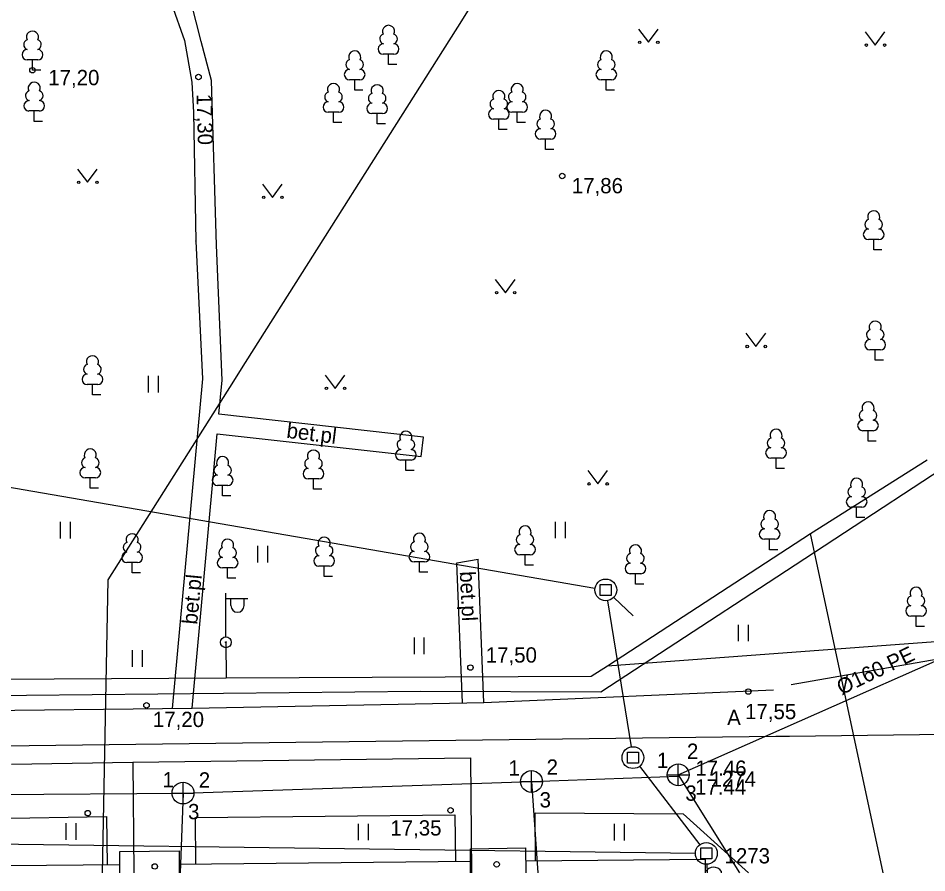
# Model space of a CAD drawing. Extents: x 713540 to 713867, y 6589774 to 6590061.
# Drawn here: x 713767.39 to 713808.98, y 6589774.07 to 6589813.21 of the extents above; entities that cross this region are included whole.
import ezdxf

# ---------------------------------------------------------------- set-up
doc = ezdxf.new("R2010")
doc.units = 0
for name, color, linetype in [('DKAEV', 7, 'Continuous'), ('HALJASTUS', 7, 'Continuous'), ('HOONE', 7, 'Continuous'), ('HOONEDET', 7, 'Continuous'), ('KKAEV', 7, 'Continuous'), ('KORGUS', 7, 'Continuous'), ('KTRASS', 7, 'Continuous'), ('MPKAABEL', 7, 'Continuous'), ('POST', 7, 'Continuous'), ('PUU', 7, 'Continuous'), ('SIKAEV', 7, 'Continuous'), ('SITRASS', 7, 'Continuous'), ('TEE', 7, 'Continuous'), ('TORU NR', 7, 'Continuous'), ('VEEKOGU', 7, 'Continuous'), ('VTRASS', 7, 'Continuous')]:
    doc.layers.add(name, color=color, linetype=linetype)

msp = doc.modelspace()

# ---------------------------------------------------------------- linework, layer by layer
at = {"layer": 'DKAEV'}
for p, q in [((713794.034, 6589786.773), (713794.034, 6589787.273)), ((713794.034, 6589787.273), (713794.534, 6589787.273)), ((713794.534, 6589787.273), (713794.534, 6589786.773)), ((713794.534, 6589786.773), (713794.034, 6589786.773)), ((713795.278, 6589779.094), (713795.278, 6589779.594)), ((713795.278, 6589779.594), (713795.778, 6589779.594)), ((713795.778, 6589779.594), (713795.778, 6589779.094)), ((713795.778, 6589779.094), (713795.278, 6589779.094)), ((713798.64, 6589774.708), (713798.64, 6589775.208)), ((713798.64, 6589775.208), (713799.14, 6589775.208)), ((713799.14, 6589775.208), (713799.14, 6589774.708)), ((713799.14, 6589774.708), (713798.64, 6589774.708))]:
    msp.add_line(p, q, dxfattribs=at)
for centre in [(713794.284, 6589787.023), (713795.528, 6589779.344), (713798.89, 6589774.958)]:
    msp.add_circle(centre, 0.5, dxfattribs=at)
at = {"layer": 'HALJASTUS'}
for p, q in [((713795.777, 6589812.707), (713796.24, 6589812.1)), ((713796.24, 6589812.1), (713796.686, 6589812.707)), ((713806.157, 6589812.577), (713806.62, 6589811.97)), ((713806.62, 6589811.97), (713807.066, 6589812.577)), ((713770.097, 6589806.297), (713770.56, 6589805.69)), ((713770.56, 6589805.69), (713771.006, 6589806.297)), ((713778.567, 6589805.607), (713779.03, 6589805)), ((713779.03, 6589805), (713779.476, 6589805.607)), ((713789.227, 6589801.237), (713789.69, 6589800.63)), ((713789.69, 6589800.63), (713790.136, 6589801.237)), ((713800.697, 6589798.777), (713801.16, 6589798.17)), ((713801.16, 6589798.17), (713801.606, 6589798.777)), ((713773.342, 6589796.823), (713773.342, 6589796.062)), ((713773.797, 6589796.823), (713773.797, 6589796.062)), ((713781.437, 6589796.857), (713781.9, 6589796.25)), ((713781.9, 6589796.25), (713782.346, 6589796.857)), ((713793.457, 6589792.487), (713793.92, 6589791.88)), ((713793.92, 6589791.88), (713794.366, 6589792.487)), ((713769.311, 6589790.145), (713769.311, 6589789.384)), ((713769.766, 6589790.145), (713769.766, 6589789.384)), ((713791.975, 6589790.148), (713791.975, 6589789.387)), ((713792.43, 6589790.148), (713792.43, 6589789.387)), ((713778.348, 6589789.036), (713778.348, 6589788.274)), ((713778.803, 6589789.036), (713778.803, 6589788.274)), ((713800.353, 6589785.432), (713800.353, 6589784.671)), ((713800.808, 6589785.432), (713800.808, 6589784.671)), ((713785.506, 6589784.849), (713785.506, 6589784.088)), ((713785.961, 6589784.849), (713785.961, 6589784.088)), ((713772.599, 6589784.263), (713772.599, 6589783.502)), ((713773.054, 6589784.263), (713773.054, 6589783.502)), ((713769.563, 6589776.344), (713769.563, 6589775.583)), ((713770.018, 6589776.344), (713770.018, 6589775.583)), ((713782.948, 6589776.318), (713782.948, 6589775.557)), ((713783.403, 6589776.318), (713783.403, 6589775.557)), ((713794.669, 6589776.314), (713794.669, 6589775.553)), ((713795.124, 6589776.314), (713795.124, 6589775.553))]:
    msp.add_line(p, q, dxfattribs=at)
for centre in [(713795.839, 6589812.1), (713796.668, 6589812.1), (713806.219, 6589811.97), (713807.048, 6589811.97), (713770.159, 6589805.69), (713770.988, 6589805.69), (713778.629, 6589805), (713779.458, 6589805), (713789.289, 6589800.63), (713790.118, 6589800.63), (713800.759, 6589798.17), (713801.588, 6589798.17), (713781.499, 6589796.25), (713782.328, 6589796.25), (713793.519, 6589791.88), (713794.348, 6589791.88)]:
    msp.add_circle(centre, 0.055, dxfattribs=at)
at = {"layer": 'HOONE'}
for points in [[(713704.798, 6589774.068), (713704.5, 6589777.88), (713726.25, 6589779.19), (713756.88, 6589779.76), (713802.063, 6589780.323), (713802.696, 6589780.331), (713812.22, 6589780.45), (713824.89, 6589807.23), (713827.83, 6589806.02)], [(713724.813, 6589799.015), (713793.791, 6589787.108)], [(713794.648, 6589786.681), (713795.546, 6589785.837)], [(713794.364, 6589786.53), (713795.448, 6589779.838)], [(713767.08, 6589779.045), (713772.63, 6589779.13), (713788.09, 6589779.34)], [(713772.63, 6589779.13), (713772.677, 6589774.068)], [(713788.09, 6589779.34), (713788.139, 6589774.068)], [(713795.832, 6589778.947), (713798.586, 6589775.355)], [(713766.244, 6589775.389), (713798.391, 6589774.964)], [(713772.046, 6589774.068), (713772.037, 6589775.043), (713774.75, 6589775.08), (713774.759, 6589774.068)], [(713788.095, 6589774.068), (713788.085, 6589775.169), (713790.615, 6589775.215), (713790.625, 6589774.068)], [(713798.909, 6589774.458), (713798.924, 6589774.068)]]:
    msp.add_lwpolyline(points, dxfattribs=at)
at = {"layer": 'KKAEV'}
for p, q in [((713790.882, 6589777.747), (713790.882, 6589778.747)), ((713797.603, 6589778.057), (713797.603, 6589779.057)), ((713797.103, 6589778.557), (713798.103, 6589778.557)), ((713774.932, 6589777.221), (713774.932, 6589778.221)), ((713790.382, 6589778.247), (713791.382, 6589778.247)), ((713774.432, 6589777.721), (713775.432, 6589777.721))]:
    msp.add_line(p, q, dxfattribs=at)
for centre in [(713790.882, 6589778.247), (713797.603, 6589778.557), (713774.932, 6589777.721)]:
    msp.add_circle(centre, 0.5, dxfattribs=at)
at = {"layer": 'KORGUS'}
for centre in [(713768.04, 6589810.82), (713775.64, 6589810.51), (713792.29, 6589805.98), (713788.09, 6589783.47), (713800.81, 6589782.37), (713773.26, 6589781.74), (713787.18, 6589776.93), (713770.57, 6589776.8), (713789.29, 6589774.46), (713773.64, 6589774.36)]:
    msp.add_circle(centre, 0.125, dxfattribs=at)
at = {"layer": 'KTRASS'}
for p, q in [((713790.882, 6589778.247), (713797.596, 6589778.501)), ((713774.932, 6589777.721), (713790.882, 6589778.247)), ((713790.882, 6589778.247), (713791.169, 6589774.068)), ((713758.53, 6589777.581), (713774.932, 6589777.721)), ((713774.932, 6589777.721), (713774.794, 6589774.068))]:
    msp.add_line(p, q, dxfattribs=at)
for points in [[(713797.603, 6589778.557), (713816.506, 6589786.914)], [(713797.603, 6589778.557), (713800.401, 6589774.068)]]:
    msp.add_lwpolyline(points, dxfattribs=at)
at = {"layer": 'MPKAABEL'}
for points in [[(713794.36, 6589783.55), (713811.85, 6589784.85), (713820.33, 6589802.68), (713827.71, 6589818.51), (713829.28, 6589821.92), (713828.25, 6589822.28), (713827.51, 6589821.7)], [(713733.277, 6589792.111), (713733.27, 6589793.4), (713736.06, 6589795.98), (713742.16, 6589795.93), (713742.89, 6589782.79), (713745.398, 6589782.812), (713776.9, 6589782.991), (713793.62, 6589783.07), (713794.36, 6589783.55), (713803.66, 6589789.6), (713809, 6589792.98)], [(713806.991, 6589774.068), (713803.66, 6589789.6)], [(713776.893, 6589784.627), (713776.9, 6589782.991)]]:
    msp.add_lwpolyline(points, dxfattribs=at)
at = {"layer": 'POST'}
for p, q in [((713776.893, 6589784.877), (713776.893, 6589786.877)), ((713776.893, 6589786.627), (713777.893, 6589786.627)), ((713777.119, 6589786.306), (713777.119, 6589786.627)), ((713777.732, 6589786.306), (713777.732, 6589786.627))]:
    msp.add_line(p, q, dxfattribs=at)
for radius in [0.25, 0.0234]:
    msp.add_circle((713776.893, 6589784.627), radius, dxfattribs=at)
msp.add_arc((713777.426, 6589786.306), 0.306, 180, 0, dxfattribs=at)
at = {"layer": 'PUU'}
for p, q in [((713784.58, 6589811.555), (713784.1, 6589811.555)), ((713784.34, 6589811.08), (713784.34, 6589811.555)), ((713768.28, 6589811.295), (713767.8, 6589811.295)), ((713768.04, 6589810.82), (713768.04, 6589811.295)), ((713768.42, 6589810.82), (713768.04, 6589810.82)), ((713784.72, 6589811.08), (713784.34, 6589811.08)), ((713783.03, 6589810.385), (713782.55, 6589810.385)), ((713782.79, 6589809.91), (713782.79, 6589810.385)), ((713794.55, 6589810.385), (713794.07, 6589810.385)), ((713794.31, 6589809.91), (713794.31, 6589810.385)), ((713783.17, 6589809.91), (713782.79, 6589809.91)), ((713794.69, 6589809.91), (713794.31, 6589809.91)), ((713768.36, 6589808.955), (713767.88, 6589808.955)), ((713768.12, 6589808.48), (713768.12, 6589808.955)), ((713782.06, 6589808.895), (713781.58, 6589808.895)), ((713781.82, 6589808.42), (713781.82, 6589808.895)), ((713784.06, 6589808.835), (713783.58, 6589808.835)), ((713783.82, 6589808.36), (713783.82, 6589808.835)), ((713790.47, 6589808.895), (713789.99, 6589808.895)), ((713790.23, 6589808.42), (713790.23, 6589808.895)), ((713768.5, 6589808.48), (713768.12, 6589808.48)), ((713782.2, 6589808.42), (713781.82, 6589808.42)), ((713784.2, 6589808.36), (713783.82, 6589808.36)), ((713789.63, 6589808.575), (713789.15, 6589808.575)), ((713789.39, 6589808.1), (713789.39, 6589808.575)), ((713790.61, 6589808.42), (713790.23, 6589808.42)), ((713789.77, 6589808.1), (713789.39, 6589808.1)), ((713791.77, 6589807.665), (713791.29, 6589807.665)), ((713791.53, 6589807.19), (713791.53, 6589807.665)), ((713791.91, 6589807.19), (713791.53, 6589807.19)), ((713806.79, 6589803.065), (713806.31, 6589803.065)), ((713806.55, 6589802.59), (713806.55, 6589803.065)), ((713806.93, 6589802.59), (713806.55, 6589802.59)), ((713806.86, 6589798.015), (713806.38, 6589798.015)), ((713806.62, 6589797.54), (713806.62, 6589798.015)), ((713807, 6589797.54), (713806.62, 6589797.54)), ((713771.025, 6589796.427), (713770.545, 6589796.427)), ((713770.785, 6589795.952), (713770.785, 6589796.427)), ((713771.165, 6589795.952), (713770.785, 6589795.952)), ((713806.53, 6589794.315), (713806.05, 6589794.315)), ((713806.29, 6589793.84), (713806.29, 6589794.315)), ((713806.67, 6589793.84), (713806.29, 6589793.84)), ((713785.373, 6589792.971), (713784.893, 6589792.971)), ((713785.133, 6589792.496), (713785.133, 6589792.971)), ((713802.32, 6589793.057), (713801.84, 6589793.057)), ((713802.08, 6589792.582), (713802.08, 6589793.057)), ((713785.513, 6589792.496), (713785.133, 6589792.496)), ((713802.46, 6589792.582), (713802.08, 6589792.582)), ((713770.926, 6589792.155), (713770.446, 6589792.155)), ((713770.686, 6589791.68), (713770.686, 6589792.155)), ((713781.145, 6589792.106), (713780.665, 6589792.106)), ((713780.905, 6589791.631), (713780.905, 6589792.106)), ((713771.066, 6589791.68), (713770.686, 6589791.68)), ((713776.985, 6589791.805), (713776.505, 6589791.805)), ((713776.745, 6589791.33), (713776.745, 6589791.805)), ((713781.285, 6589791.631), (713780.905, 6589791.631)), ((713777.125, 6589791.33), (713776.745, 6589791.33)), ((713806.01, 6589790.815), (713805.53, 6589790.815)), ((713805.77, 6589790.34), (713805.77, 6589790.815)), ((713806.15, 6589790.34), (713805.77, 6589790.34)), ((713802.027, 6589789.341), (713801.547, 6589789.341)), ((713801.787, 6589788.866), (713801.787, 6589789.341)), ((713802.167, 6589788.866), (713801.787, 6589788.866)), ((713772.842, 6589788.276), (713772.362, 6589788.276)), ((713772.602, 6589787.801), (713772.602, 6589788.276)), ((713785.992, 6589788.304), (713785.512, 6589788.304)), ((713785.752, 6589787.829), (713785.752, 6589788.304)), ((713790.83, 6589788.63), (713790.35, 6589788.63)), ((713790.59, 6589788.155), (713790.59, 6589788.63)), ((713777.215, 6589788.03), (713776.735, 6589788.03)), ((713776.975, 6589787.555), (713776.975, 6589788.03)), ((713781.634, 6589788.112), (713781.154, 6589788.112)), ((713781.394, 6589787.637), (713781.394, 6589788.112)), ((713790.97, 6589788.155), (713790.59, 6589788.155)), ((713772.982, 6589787.801), (713772.602, 6589787.801)), ((713777.355, 6589787.555), (713776.975, 6589787.555)), ((713781.774, 6589787.637), (713781.394, 6589787.637)), ((713786.132, 6589787.829), (713785.752, 6589787.829)), ((713795.883, 6589787.767), (713795.403, 6589787.767)), ((713795.643, 6589787.292), (713795.643, 6589787.767)), ((713796.023, 6589787.292), (713795.643, 6589787.292)), ((713808.73, 6589785.825), (713808.25, 6589785.825)), ((713808.49, 6589785.35), (713808.49, 6589785.825)), ((713808.87, 6589785.35), (713808.49, 6589785.35))]:
    msp.add_line(p, q, dxfattribs=at)
for centre, radius, start, end in [((713784.34, 6589812.6), 0.277, 332.5799, 207.4201), ((713768.04, 6589812.34), 0.277, 332.5799, 207.4201), ((713784.17, 6589812.253), 0.233, 109.0217, 253.1415), ((713784.51, 6589812.253), 0.233, 286.8508, 70.9859), ((713767.87, 6589811.993), 0.233, 109.0217, 253.1415), ((713768.21, 6589811.993), 0.233, 286.8508, 70.9859), ((713784.103, 6589811.792), 0.238, 90.0016, 269.3953), ((713784.577, 6589811.792), 0.238, 270.6047, 89.9984), ((713767.803, 6589811.532), 0.238, 90.0016, 269.3953), ((713768.277, 6589811.532), 0.238, 270.6047, 89.9984), ((713782.79, 6589811.43), 0.277, 332.5799, 207.4201), ((713794.31, 6589811.43), 0.277, 332.5799, 207.4201), ((713782.62, 6589811.083), 0.233, 109.0217, 253.1415), ((713782.96, 6589811.083), 0.233, 286.8508, 70.9859), ((713794.14, 6589811.083), 0.233, 109.0217, 253.1415), ((713794.48, 6589811.083), 0.233, 286.8508, 70.9859), ((713782.553, 6589810.622), 0.238, 90.0016, 269.3953), ((713783.027, 6589810.622), 0.238, 270.6047, 89.9984), ((713794.073, 6589810.622), 0.238, 90.0016, 269.3953), ((713794.547, 6589810.622), 0.238, 270.6047, 89.9984), ((713768.12, 6589810), 0.277, 332.5799, 207.4201), ((713781.82, 6589809.94), 0.277, 332.5799, 207.4201), ((713783.82, 6589809.88), 0.277, 332.5799, 207.4201), ((713789.39, 6589809.62), 0.277, 332.5799, 207.4201), ((713790.23, 6589809.94), 0.277, 332.5799, 207.4201), ((713767.95, 6589809.653), 0.233, 109.0217, 253.1415), ((713768.29, 6589809.653), 0.233, 286.8508, 70.9859), ((713781.65, 6589809.593), 0.233, 109.0217, 253.1415), ((713781.99, 6589809.593), 0.233, 286.8508, 70.9859), ((713783.65, 6589809.533), 0.233, 109.0217, 253.1415), ((713783.99, 6589809.533), 0.233, 286.8508, 70.9859), ((713789.22, 6589809.273), 0.233, 109.0217, 253.1415), ((713789.56, 6589809.273), 0.233, 286.8508, 70.9859), ((713790.06, 6589809.593), 0.233, 109.0217, 253.1415), ((713790.4, 6589809.593), 0.233, 286.8508, 70.9859), ((713767.883, 6589809.192), 0.238, 90.0016, 269.3953), ((713768.357, 6589809.192), 0.238, 270.6047, 89.9984), ((713781.583, 6589809.132), 0.238, 90.0016, 269.3953), ((713782.057, 6589809.132), 0.238, 270.6047, 89.9984), ((713783.583, 6589809.072), 0.238, 90.0016, 269.3953), ((713784.057, 6589809.072), 0.238, 270.6047, 89.9984), ((713789.993, 6589809.132), 0.238, 90.0016, 269.3953), ((713790.467, 6589809.132), 0.238, 270.6047, 89.9984), ((713789.153, 6589808.812), 0.238, 90.0016, 269.3953), ((713789.627, 6589808.812), 0.238, 270.6047, 89.9984), ((713791.53, 6589808.71), 0.277, 332.5799, 207.4201), ((713791.36, 6589808.363), 0.233, 109.0217, 253.1415), ((713791.7, 6589808.363), 0.233, 286.8508, 70.9859), ((713791.293, 6589807.902), 0.238, 90.0016, 269.3953), ((713791.767, 6589807.902), 0.238, 270.6047, 89.9984), ((713806.55, 6589804.11), 0.277, 332.5799, 207.4201), ((713806.38, 6589803.763), 0.233, 109.0217, 253.1415), ((713806.72, 6589803.763), 0.233, 286.8508, 70.9859), ((713806.313, 6589803.302), 0.238, 90.0016, 269.3953), ((713806.787, 6589803.302), 0.238, 270.6047, 89.9984), ((713806.62, 6589799.06), 0.277, 332.5799, 207.4201), ((713806.45, 6589798.713), 0.233, 109.0217, 253.1415), ((713806.79, 6589798.713), 0.233, 286.8508, 70.9859), ((713806.383, 6589798.252), 0.238, 90.0016, 269.3953), ((713806.857, 6589798.252), 0.238, 270.6047, 89.9984), ((713770.785, 6589797.472), 0.277, 332.5799, 207.4201), ((713770.615, 6589797.125), 0.233, 109.0217, 253.1415), ((713770.955, 6589797.125), 0.233, 286.8508, 70.9859), ((713770.547, 6589796.665), 0.238, 90.0016, 269.3953), ((713771.022, 6589796.665), 0.238, 270.6047, 89.9984), ((713806.29, 6589795.36), 0.277, 332.5799, 207.4201), ((713806.12, 6589795.013), 0.233, 109.0217, 253.1415), ((713806.46, 6589795.013), 0.233, 286.8508, 70.9859), ((713806.053, 6589794.552), 0.238, 90.0016, 269.3953), ((713806.527, 6589794.552), 0.238, 270.6047, 89.9984), ((713785.133, 6589794.016), 0.277, 332.5799, 207.4201), ((713802.08, 6589794.102), 0.277, 332.5799, 207.4201), ((713784.963, 6589793.669), 0.233, 109.0217, 253.1415), ((713785.304, 6589793.669), 0.233, 286.8508, 70.9859), ((713801.91, 6589793.754), 0.233, 109.0217, 253.1415), ((713802.25, 6589793.754), 0.233, 286.8508, 70.9859), ((713770.686, 6589793.2), 0.277, 332.5799, 207.4201), ((713780.905, 6589793.151), 0.277, 332.5799, 207.4201), ((713784.896, 6589793.209), 0.238, 90.0016, 269.3953), ((713785.371, 6589793.209), 0.238, 270.6047, 89.9984), ((713801.842, 6589793.294), 0.238, 90.0016, 269.3953), ((713802.317, 6589793.294), 0.238, 270.6047, 89.9984), ((713770.516, 6589792.853), 0.233, 109.0217, 253.1415), ((713770.856, 6589792.853), 0.233, 286.8508, 70.9859), ((713776.745, 6589792.85), 0.277, 332.5799, 207.4201), ((713780.735, 6589792.803), 0.233, 109.0217, 253.1415), ((713781.075, 6589792.803), 0.233, 286.8508, 70.9859), ((713770.449, 6589792.392), 0.238, 90.0016, 269.3953), ((713770.924, 6589792.392), 0.238, 270.6047, 89.9984), ((713776.575, 6589792.503), 0.233, 109.0217, 253.1415), ((713776.915, 6589792.503), 0.233, 286.8508, 70.9859), ((713780.668, 6589792.343), 0.238, 90.0016, 269.3953), ((713781.143, 6589792.343), 0.238, 270.6047, 89.9984), ((713776.507, 6589792.043), 0.238, 90.0016, 269.3953), ((713776.982, 6589792.043), 0.238, 270.6047, 89.9984), ((713805.77, 6589791.86), 0.277, 332.5799, 207.4201), ((713805.6, 6589791.513), 0.233, 109.0217, 253.1415), ((713805.94, 6589791.513), 0.233, 286.8508, 70.9859), ((713805.533, 6589791.052), 0.238, 90.0016, 269.3953), ((713806.007, 6589791.052), 0.238, 270.6047, 89.9984), ((713801.787, 6589790.386), 0.277, 332.5799, 207.4201), ((713790.59, 6589789.675), 0.277, 332.5799, 207.4201), ((713801.617, 6589790.038), 0.233, 109.0217, 253.1415), ((713801.957, 6589790.038), 0.233, 286.8508, 70.9859), ((713772.602, 6589789.321), 0.277, 332.5799, 207.4201), ((713785.752, 6589789.349), 0.277, 332.5799, 207.4201), ((713790.42, 6589789.328), 0.233, 109.0217, 253.1415), ((713790.76, 6589789.328), 0.233, 286.8508, 70.9859), ((713801.549, 6589789.578), 0.238, 90.0016, 269.3953), ((713802.024, 6589789.578), 0.238, 270.6047, 89.9984), ((713772.432, 6589788.973), 0.233, 109.0217, 253.1415), ((713772.772, 6589788.973), 0.233, 286.8508, 70.9859), ((713776.975, 6589789.075), 0.277, 332.5799, 207.4201), ((713781.394, 6589789.157), 0.277, 332.5799, 207.4201), ((713785.582, 6589789.001), 0.233, 109.0217, 253.1415), ((713785.922, 6589789.001), 0.233, 286.8508, 70.9859), ((713790.352, 6589788.868), 0.238, 90.0016, 269.3953), ((713790.827, 6589788.868), 0.238, 270.6047, 89.9984), ((713795.643, 6589788.812), 0.277, 332.5799, 207.4201), ((713772.365, 6589788.513), 0.238, 90.0016, 269.3953), ((713772.84, 6589788.513), 0.238, 270.6047, 89.9984), ((713776.805, 6589788.728), 0.233, 109.0217, 253.1415), ((713777.145, 6589788.728), 0.233, 286.8508, 70.9859), ((713781.224, 6589788.81), 0.233, 109.0217, 253.1415), ((713781.564, 6589788.81), 0.233, 286.8508, 70.9859), ((713785.514, 6589788.541), 0.238, 90.0016, 269.3953), ((713785.989, 6589788.541), 0.238, 270.6047, 89.9984), ((713795.473, 6589788.465), 0.233, 109.0217, 253.1415), ((713795.813, 6589788.465), 0.233, 286.8508, 70.9859), ((713776.737, 6589788.268), 0.238, 90.0016, 269.3953), ((713777.212, 6589788.268), 0.238, 270.6047, 89.9984), ((713781.157, 6589788.349), 0.238, 90.0016, 269.3953), ((713781.632, 6589788.349), 0.238, 270.6047, 89.9984), ((713795.406, 6589788.005), 0.238, 90.0016, 269.3953), ((713795.881, 6589788.005), 0.238, 270.6047, 89.9984), ((713808.49, 6589786.87), 0.277, 332.5799, 207.4201), ((713808.32, 6589786.523), 0.233, 109.0217, 253.1415), ((713808.66, 6589786.523), 0.233, 286.8508, 70.9859), ((713808.253, 6589786.062), 0.238, 90.0016, 269.3953), ((713808.727, 6589786.062), 0.238, 270.6047, 89.9984)]:
    msp.add_arc(centre, radius, start, end, dxfattribs=at)
at = {"layer": 'SITRASS'}
msp.add_lwpolyline([(713726.305, 6589783.201), (713726.59, 6589783.58), (713728.41, 6589783.99), (713737.91, 6589784.56), (713742.79, 6589781.97), (713755.73, 6589782.08), (713785.81, 6589782.39), (713794.06, 6589782.35), (713801.725, 6589787.367), (713802.954, 6589788.171), (713811.95, 6589794.06), (713820.13, 6589802.81), (713825.16, 6589813.2), (713832.56, 6589810.04)], dxfattribs=at)
at = {"layer": 'TEE'}
for points in [[(713771.12, 6589822.71), (713773.03, 6589817.14), (713774.41, 6589813.86), (713775, 6589812.19), (713775.33, 6589810.27), (713775.41, 6589808.89), (713775.523, 6589802.99), (713775.52, 6589803.002), (713775.523, 6589802.99), (713775.82, 6589796.687), (713774.442, 6589781.6)], [(713775.346, 6589781.61), (713776.493, 6589794.168), (713785.839, 6589793.127), (713785.938, 6589794.022), (713776.575, 6589795.065), (713776.717, 6589796.622), (713776.469, 6589802.811), (713776.23, 6589810.35), (713775.76, 6589812.13), (713775.31, 6589813.94), (713773.93, 6589817.22), (713771.94, 6589822.75)], [(713787.474, 6589788.262), (713788.444, 6589788.436)], [(713787.722, 6589781.849), (713787.474, 6589788.262)], [(713788.698, 6589781.868), (713788.444, 6589788.436)], [(713813.12, 6589786.46), (713812.47, 6589785.05), (713812.03, 6589784.3), (713802.773, 6589782.673)], [(713737.195, 6589781.213), (713753.691, 6589781.368), (713775.346, 6589781.61), (713788.698, 6589781.868), (713801.96, 6589782.454)], [(713759.151, 6589774.31), (713759.132, 6589776.432), (713771.432, 6589776.643), (713771.453, 6589774.425)], [(713775.518, 6589774.463), (713775.498, 6589776.608), (713787.382, 6589776.717), (713787.402, 6589774.574)], [(713791.074, 6589774.609), (713791.053, 6589776.822), (713797.824, 6589776.768)], [(713800.814, 6589774.068), (713797.824, 6589776.768)], [(713788.091, 6589774.581), (713774.755, 6589774.456)], [(713798.854, 6589774.068), (713798.849, 6589774.681), (713790.62, 6589774.604)], [(713772.043, 6589774.431), (713758.618, 6589774.305)]]:
    msp.add_lwpolyline(points, dxfattribs=at)
at = {"layer": 'VEEKOGU'}
for points in [[(713798.853, 6589774.068), (713798.853, 6589774.132)], [(713799.569, 6589774.138), (713799.569, 6589774.068)]]:
    msp.add_lwpolyline(points, dxfattribs=at)
msp.add_arc((713799.213, 6589773.893), 0.432, 34.4244, 146.4047, dxfattribs=at)
at = {"layer": 'VTRASS'}
msp.add_lwpolyline([(713771.246, 6589774.068), (713771.5, 6589787.48), (713777.257, 6589796.582), (713777.609, 6589797.14), (713787.69, 6589813.08), (713794.35, 6589823.75)], dxfattribs=at)

# ---------------------------------------------------------------- texts
at = {"layer": 'HOONEDET'}
for rotation, p in [(352.8785, (713779.643, 6589793.992)), (84.5936, (713775.577, 6589785.42)), (272.8077, (713787.599, 6589787.863))]:
    msp.add_text('bet.pl', height=0.7, rotation=rotation, dxfattribs=at).set_placement(p)
at = {"layer": 'KORGUS'}
for s, p in [('17,20', (713768.761, 6589810.135)), ('17,86', (713792.73, 6589805.185)), ('17,50', (713788.791, 6589783.695)), ('17,55', (713800.663, 6589781.105)), ('17,20', (713773.551, 6589780.745)), ('17.46', (713798.387, 6589778.511)), ('17.44', (713798.374, 6589777.647)), ('17,35', (713784.423, 6589775.775))]:
    msp.add_text(s, height=0.7, dxfattribs=at).set_placement(p)
msp.add_text('17,30', height=0.7, rotation=271.5014, dxfattribs=at).set_placement((713775.552, 6589809.731))
at = {"layer": 'KTRASS'}
msp.add_text('%%c160 PE', height=0.7, rotation=25.6958, dxfattribs=at).set_placement((713805.071, 6589782.199))
at = {"layer": 'SIKAEV'}
for s, p in [('1274', (713799.08, 6589778.02)), ('1273', (713799.72, 6589774.5))]:
    msp.add_text(s, height=0.7, dxfattribs=at).set_placement(p)
at = {"layer": 'TEE'}
msp.add_text('A', height=0.7, dxfattribs=at).set_placement((713799.843, 6589780.834))
at = {"layer": 'TORU NR'}
for s, p in [('2', (713798.001, 6589779.286)), ('1', (713796.625, 6589778.868)), ('1', (713789.831, 6589778.524)), ('2', (713791.576, 6589778.561)), ('1', (713773.994, 6589777.983)), ('2', (713775.653, 6589777.971)), ('3', (713797.928, 6589777.369)), ('3', (713791.256, 6589777.062)), ('3', (713775.162, 6589776.521))]:
    msp.add_text(s, height=0.7, dxfattribs=at).set_placement(p)

doc.saveas('drawing.dxf')
